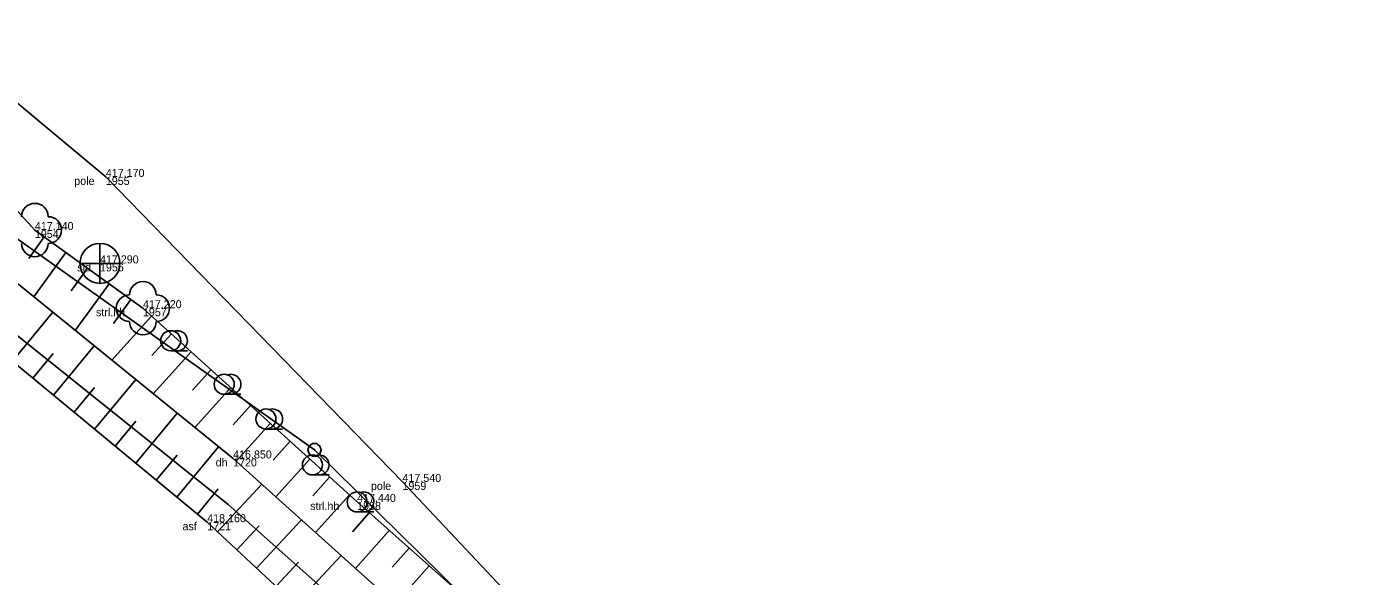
# Model space of a CAD drawing. Extents: x -747792 to -745414, y -1093712 to -1091463.
# Drawn here: x -746752.3 to -746701.9, y -1092404.7 to -1092384.1 of the extents above; entities that cross this region are included whole.
import ezdxf

# ---------------------------------------------------------------- set-up
doc = ezdxf.new("R2010")
doc.units = 0
for name, color, linetype in [('Doplňující texty', 7, 'Continuous'), ('Hladina', 7, 'Continuous'), ('Nivelační značky_hrany', 7, 'Continuous'), ('Pracovní_bod JDTM STC_VC - výška', 7, 'Continuous'), ('Pracovní_bod PPBP', 7, 'Continuous'), ('Pracovní_bod PPBP - číslo', 7, 'Continuous'), ('Rozhraní ploch', 7, 'Continuous'), ('Stromy_porost', 7, 'Continuous'), ('Výškopis', 7, 'Continuous'), ('Čísla popisná_parcelní', 7, 'Continuous')]:
    doc.layers.add(name, color=color, linetype=linetype)

msp = doc.modelspace()

# ---------------------------------------------------------------- linework, layer by layer
at = {"layer": 'Doplňující texty'}
msp.add_lwpolyline([(-746741.475, -1092399.71), (-746741.35, -1092399.805), (-746741.3, -1092399.95), (-746741.35, -1092400.095), (-746741.475, -1092400.19), (-746741.625, -1092400.19), (-746741.75, -1092400.095), (-746741.8, -1092399.95), (-746741.75, -1092399.805), (-746741.625, -1092399.71)], close=True, dxfattribs=at)
msp.add_lwpolyline([(-746741.575, -1092399.95), (-746741.525, -1092399.95)], dxfattribs=at)
at = {"layer": 'Hladina'}
for p, q in [((-746749.37, -1092389.72), (-746749.37, -1092389.72)), ((-746752.03, -1092391.71), (-746752.03, -1092391.71)), ((-746749.59, -1092392.96), (-746749.59, -1092392.96)), ((-746747.98, -1092394.64), (-746747.98, -1092394.64)), ((-746744.6, -1092400.27), (-746744.6, -1092400.27)), ((-746738.25, -1092401.15), (-746738.25, -1092401.15)), ((-746739.95, -1092401.9), (-746739.95, -1092401.9)), ((-746745.57, -1092402.66), (-746745.57, -1092402.66))]:
    msp.add_line(p, q, dxfattribs=at)
at = {"layer": 'Nivelační značky_hrany'}
msp.add_lwpolyline([(-746808.227, -1092357.17), (-746797.53, -1092364.29), (-746787.69, -1092371.13), (-746776.62, -1092378.78), (-746765.54, -1092386.79), (-746755.3, -1092394.62), (-746745.57, -1092402.66), (-746737.91, -1092409.79), (-746728.85, -1092419.26), (-746722.7, -1092426.86), (-746714.67, -1092437.95), (-746707.62, -1092449.35), (-746700.44, -1092461.3), (-746693.84, -1092472.82), (-746684.01, -1092490.2), (-746680.08, -1092497.02)], dxfattribs=at)
at = {"layer": 'Pracovní_bod JDTM STC_VC - výška'}
msp.add_lwpolyline([(-746666.48, -1092509.53), (-746671.18, -1092501.38), (-746679.28, -1092488.1), (-746683.01, -1092480.66), (-746691.02, -1092465.89), (-746695.91, -1092457.38), (-746697.67, -1092451.5), (-746700.29, -1092444.13), (-746704.56, -1092439.88), (-746720.11, -1092421.5), (-746727.2, -1092412.89), (-746738.25, -1092401.15), (-746749.37, -1092389.72), (-746764.79, -1092376.86), (-746776.64, -1092368.43), (-746787.43, -1092361.47), (-746799.53, -1092355.13), (-746817.34, -1092343.1), (-746824.75, -1092337.86), (-746838.2, -1092329.38), (-746851.64, -1092319.28)], dxfattribs=at)
for centre in [(-746752.03, -1092391.71), (-746747.98, -1092394.64)]:
    msp.add_circle(centre, 0.0005, dxfattribs=at)
for centre, start, end in [((-746752.03, -1092391.21), 0, 180), ((-746751.53, -1092391.71), 270, 90), ((-746752.03, -1092392.21), 180, 360), ((-746747.98, -1092394.14), 0, 180), ((-746748.48, -1092394.64), 90, 270), ((-746747.48, -1092394.64), 270, 90), ((-746747.98, -1092395.14), 180, 360)]:
    msp.add_arc(centre, 0.5, start, end, dxfattribs=at)
at = {"layer": 'Pracovní_bod PPBP'}
for points in [[(-746676.31, -1092494.93), (-746679.28, -1092488.1), (-746684.61, -1092481.19), (-746692.58, -1092466.75), (-746703.9, -1092446.01), (-746716.46, -1092426.76), (-746727.325, -1092413.107), (-746739.95, -1092401.9), (-746747.98, -1092394.64), (-746752.03, -1092391.71), (-746753.83, -1092389.76), (-746758.64, -1092386.23), (-746765.82, -1092381.07), (-746787.5, -1092365.52), (-746806.41, -1092354.03)], [(-746807.12, -1092355.24), (-746796.58, -1092362.79), (-746786.63, -1092368.73), (-746775.02, -1092376.93), (-746764.6, -1092384.11), (-746753.89, -1092392.74), (-746744.6, -1092400.27), (-746734.99, -1092408.91), (-746726.93, -1092417.05), (-746720.19, -1092425.45), (-746712.76, -1092435.88), (-746705, -1092448.32), (-746698.55, -1092460.04), (-746691.76, -1092472.37), (-746682.53, -1092488.74), (-746678.42, -1092495.91)], [(-746751.677, -1092391.965), (-746752.263, -1092392.775)], [(-746750.867, -1092392.551), (-746752.07, -1092394.215)], [(-746750.057, -1092393.138), (-746750.674, -1092393.992)], [(-746749.246, -1092393.724), (-746750.514, -1092395.476)], [(-746748.436, -1092394.31), (-746749.086, -1092395.208)], [(-746752.874, -1092396.625), (-746751.359, -1092394.791)], [(-746747.656, -1092394.933), (-746749.148, -1092396.583)], [(-746746.914, -1092395.604), (-746747.642, -1092396.409)], [(-746752.103, -1092397.262), (-746751.343, -1092396.341)], [(-746751.332, -1092397.898), (-746749.805, -1092396.051)], [(-746746.172, -1092396.274), (-746747.592, -1092397.845)], [(-746749.791, -1092399.172), (-746748.252, -1092397.31)], [(-746745.431, -1092396.945), (-746746.122, -1092397.71)], [(-746750.561, -1092398.535), (-746749.795, -1092397.608)], [(-746744.689, -1092397.616), (-746746.036, -1092399.106)], [(-746743.947, -1092398.286), (-746744.603, -1092399.011)], [(-746749.02, -1092399.809), (-746748.247, -1092398.875)], [(-746748.249, -1092400.446), (-746746.698, -1092398.57)], [(-746743.205, -1092398.957), (-746744.486, -1092400.373)], [(-746746.707, -1092401.72), (-746745.144, -1092399.829)], [(-746742.464, -1092399.628), (-746743.103, -1092400.335)], [(-746747.478, -1092401.083), (-746746.7, -1092400.141)], [(-746741.722, -1092400.298), (-746742.998, -1092401.71)], [(-746745.936, -1092402.357), (-746745.157, -1092401.414)], [(-746745.186, -1092403.018), (-746743.527, -1092401.235)], [(-746740.98, -1092400.969), (-746741.617, -1092401.674)], [(-746740.238, -1092401.639), (-746741.511, -1092403.047)], [(-746739.493, -1092402.306), (-746740.124, -1092403.017)], [(-746744.454, -1092403.699), (-746743.618, -1092402.801)], [(-746743.722, -1092404.38), (-746742.039, -1092402.572)], [(-746738.745, -1092402.97), (-746740.011, -1092404.396)], [(-746742.258, -1092405.743), (-746740.552, -1092403.91)], [(-746737.997, -1092403.634), (-746738.632, -1092404.349)], [(-746742.99, -1092405.062), (-746742.143, -1092404.151)], [(-746737.249, -1092404.298), (-746738.523, -1092405.733)]]:
    msp.add_lwpolyline(points, dxfattribs=at)
at = {"layer": 'Pracovní_bod PPBP - číslo'}
for p, q in [((-746746.94, -1092396.234), (-746746.315, -1092396.234)), ((-746744.933, -1092397.866), (-746744.308, -1092397.866)), ((-746743.368, -1092399.167), (-746742.743, -1092399.167)), ((-746741.626, -1092400.887), (-746741.001, -1092400.887)), ((-746739.95, -1092402.275), (-746739.325, -1092402.275))]:
    msp.add_line(p, q, dxfattribs=at)
for centre in [(-746746.94, -1092395.859), (-746744.933, -1092397.491), (-746743.368, -1092398.792), (-746741.626, -1092400.512), (-746739.95, -1092401.9)]:
    msp.add_circle(centre, 0.375, dxfattribs=at)
for centre in [(-746746.69, -1092395.859), (-746744.683, -1092397.491), (-746743.118, -1092398.792), (-746741.376, -1092400.512), (-746739.7, -1092401.9)]:
    msp.add_arc(centre, 0.375, 249.4944, 109.0474, dxfattribs=at)
at = {"layer": 'Stromy_porost'}
for points in [[(-746799.83, -1092358.59), (-746741.55, -1092399.95)], [(-746744.79, -1092401.99), (-746756.74, -1092392.43)], [(-746720.95, -1092420.21), (-746741.55, -1092399.95)], [(-746728.49, -1092416.47), (-746744.79, -1092401.99)]]:
    msp.add_lwpolyline(points, dxfattribs=at)
at = {"layer": 'Čísla popisná_parcelní'}
for p, q in [((-746749.591, -1092393.708), (-746749.59, -1092392.213)), ((-746748.838, -1092392.966), (-746750.338, -1092392.961))]:
    msp.add_line(p, q, dxfattribs=at)
msp.add_circle((-746749.59, -1092392.96), 0.75, dxfattribs=at)

# ---------------------------------------------------------------- texts
at = {"layer": 'Rozhraní ploch'}
for s, p in [(' pole', (-746750.664, -1092390.02)), ('1955', (-746749.37, -1092390.02)), ('1954', (-746752.03, -1092392.01)), (' sld', (-746750.551, -1092393.26)), ('1956', (-746749.59, -1092393.26)), (' strl.hh', (-746749.851, -1092394.94)), ('1957', (-746747.98, -1092394.94)), (' dh', (-746745.365, -1092400.57)), ('1720', (-746744.6, -1092400.57)), (' pole', (-746739.544, -1092401.45)), ('1959', (-746738.25, -1092401.45)), (' strl.hh', (-746741.821, -1092402.2)), ('1958', (-746739.95, -1092402.2)), (' asf', (-746746.607, -1092402.96)), ('1721', (-746745.57, -1092402.96))]:
    msp.add_text(s, height=0.3, dxfattribs=at).set_placement(p)
at = {"layer": 'Výškopis'}
for s, p in [('417,170', (-746749.37, -1092389.72)), ('417,140', (-746752.03, -1092391.71)), ('417,290', (-746749.59, -1092392.96)), ('417,220', (-746747.98, -1092394.64)), ('416,850', (-746744.6, -1092400.27)), ('417,540', (-746738.25, -1092401.15)), ('417,440', (-746739.95, -1092401.9)), ('418,160', (-746745.57, -1092402.66))]:
    msp.add_text(s, height=0.3, dxfattribs=at).set_placement(p)

doc.saveas('drawing.dxf')
